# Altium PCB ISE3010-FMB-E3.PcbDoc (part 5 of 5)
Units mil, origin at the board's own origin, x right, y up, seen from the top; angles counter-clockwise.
Board outline 7874.02 x 2362.2 mil, 4 copper layers (Top Layer, MidLayer1, MidLayer2, Bottom Layer), stack 55.6 mil thick; 507 components, 331 nets, 1707 pads, 610 vias.
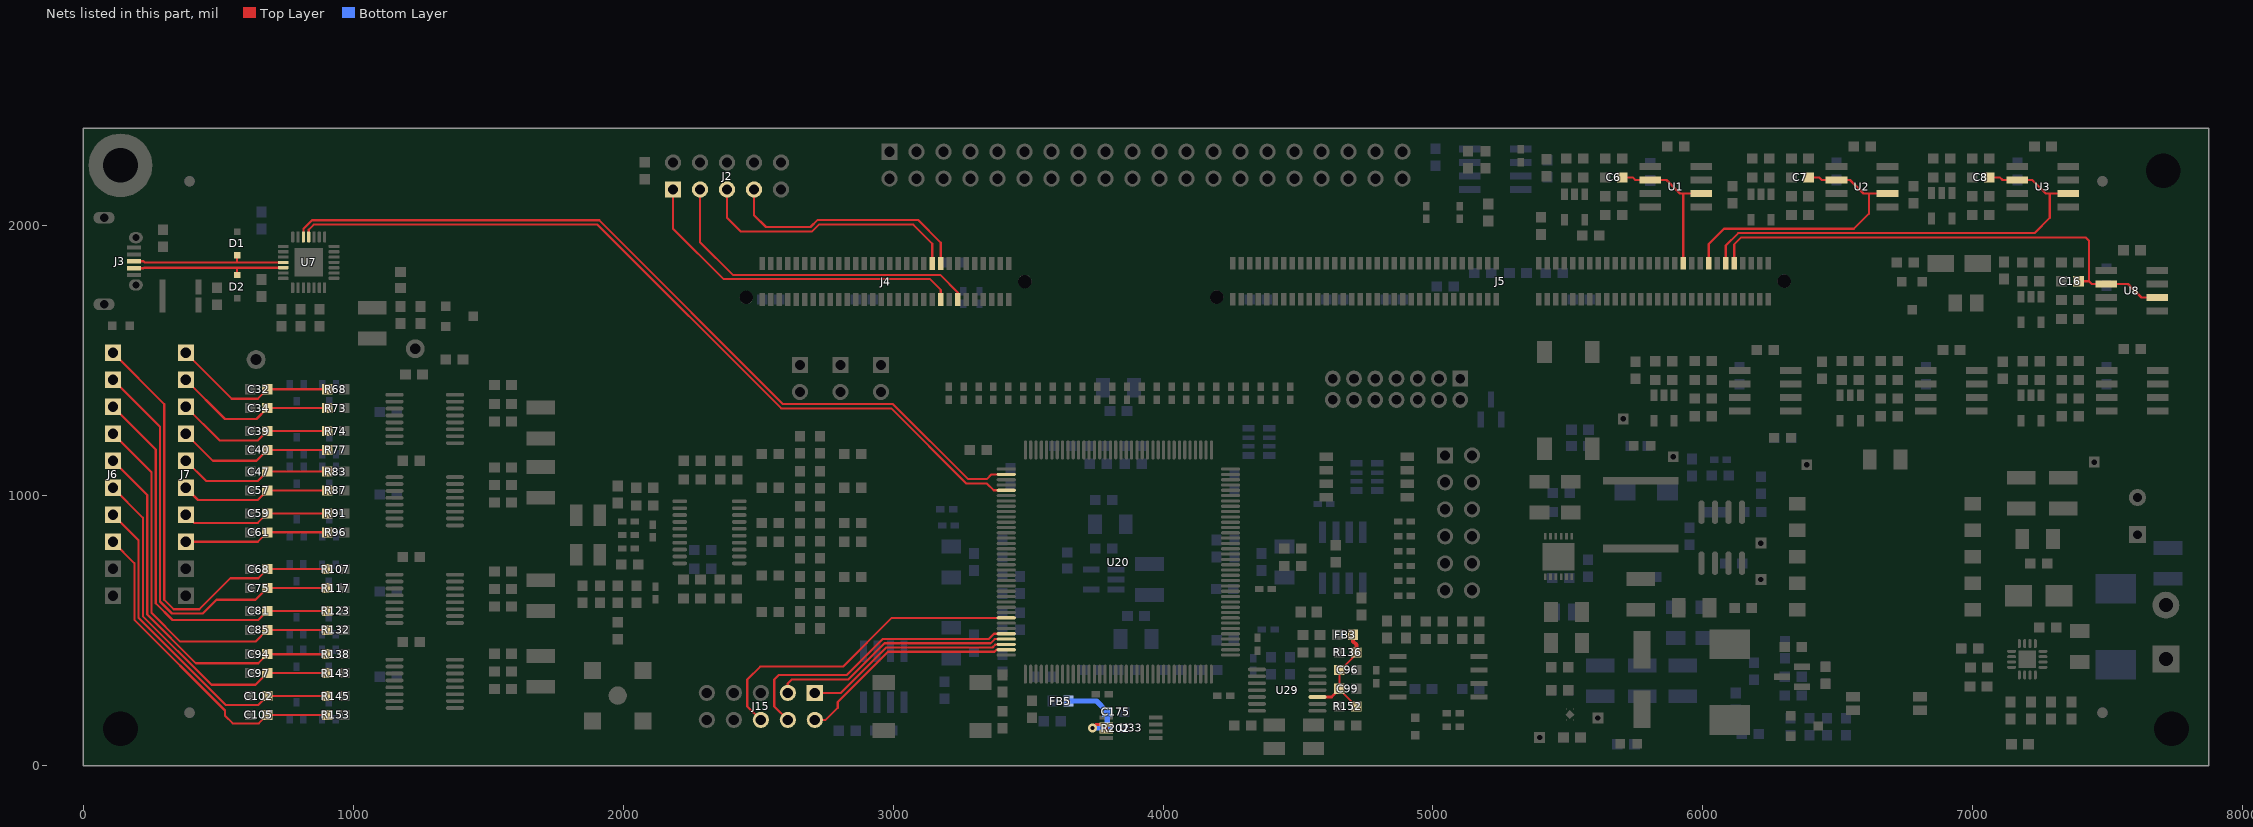
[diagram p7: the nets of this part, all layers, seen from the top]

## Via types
v1: diameter 32, hole 16, Top Layer to Bottom Layer, tented both sides, 495 vias
v2: diameter 26, hole 12, Top Layer to Bottom Layer, tented both sides, 104 vias
v3: diameter 20, hole 8, Top Layer to Bottom Layer, tented both sides, 10 vias
v4: diameter 30, hole 16, Top Layer to Bottom Layer, tented both sides, 1 vias

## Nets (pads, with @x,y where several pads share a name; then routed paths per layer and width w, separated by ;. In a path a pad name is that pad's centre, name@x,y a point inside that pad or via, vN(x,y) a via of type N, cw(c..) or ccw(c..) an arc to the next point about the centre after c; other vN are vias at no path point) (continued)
SC_ALARM_FPGA: J15.6 U20.29 | length 1224.5
  Top Layer w8: J15.6@2510,170 2460,220 2460,320 2507.4,367.4 2814.43,367.4 2995.18,548.15 U20.29@3419.29,548.15
SH_U_ADCIN: C16.2 J5.9 U8.2 U8.6 | length 1867.1
  Top Layer w8: J5.9@6116.14,1861.93 6116.14,1931.65 6142.19,1957.7 7417.3,1957.7 7430.31,1944.69 7430.31,1795 ; C16.2@7391.81,1795 7430.31,1795 ; U8.6@7684.31,1735 U8.6@7684,1735 7625,1735 7575,1785 U8.2@7495,1785 7440.31,1785 7430.31,1795
SH_V_ADCIN: C8.2 J5.11 U3.2 U3.6 | length 1715.7
  Top Layer w8: J5.11@6084.65,1861.93 6084.65,1927.44 6130.71,1973.5 7228.5,1973.5 7285,2030 7285,2120 ; C8.2@7061.5,2180 7100,2180 7110,2170 U3.2@7165,2170 7220,2170 7270,2120 7285,2120 ; U3.6@7354,2120 7285,2120
SH_W_ADCIN: C7.2 J5.15 U2.2 U2.6 | length 1103
  Top Layer w8: J5.15@6021.65,1861.93 6021.65,1932.8 6078.16,1989.3 6559.3,1989.3 6615,2045 6615,2120 ; C7.2@6391.5,2180 6430,2180 6440,2170 U2.2@6495,2170 6545.07,2170 6595.07,2120 6615,2120 ; U2.6@6684,2120 6615,2120
SPI_CLK: J2.1 J4.138 | length 1266.9
  Top Layer w8: J2.1@2185,2135 2185,1990 2372.2,1802.8 3137.2,1802.8 3176.91,1763.09 J4.138@3176.91,1727.07
SPI_CLK_FPGA: J15.3 U20.33 | length 912.4
  Top Layer w8: J15.3@2610,270 2610,305 2625,320 2834.07,320 2968.27,454.2 3361.54,454.2 3376.75,469.41 U20.33@3419.29,469.41
SPI_MISO: J2.7 J4.137 | length 928.5
  Top Layer w8: J2.7@2485,2135 2485,2040 2529.2,1995.8 2693.88,1995.8 2720.68,2022.6 3092.4,2022.6 3176.91,1938.09 J4.137@3176.91,1860.93
SPI_MISO_FPGA: J15.1 U20.34 | length 783.6
  Top Layer w8: J15.1@2710,270 2806.41,270 2974.81,438.4 3368.09,438.4 3378.52,448.83 ; 3378.67,448.67 3379.72,449.72 U20.34@3419.29,449.72
SPI_MOSI: J2.3 J4.134 | length 1253.3
  Top Layer w8: J2.3@2285,2135 2285,1940 2406.4,1818.6 3174.4,1818.6 3239.9,1753.1 J4.134@3239.9,1727.07
SPI_MOSI_FPGA: J15.2 U20.35 | length 829.4
  Top Layer w8: J15.2@2710,170 2750,170 2795,215 2795,236.24 2981.36,422.6 3375.58,422.6 3383.02,430.04 U20.35@3419.29,430.04
SPI_STE: J2.5 J4.139 | length 999.3
  Top Layer w8: J2.5@2385,2135 2385,2030 2435,1980 2700,1980 2725,2005 3075,2005 3145.41,1934.59 J4.139@3145.41,1860.93
SPI_STE_FPGA: J15.4 U20.32 | length 1100
  Top Layer w8: J15.4@2610,170 2560,220 2560,320 2575.8,335.8 2827.52,335.8 2961.72,470 3355,470 3374.09,489.09 U20.32@3419.29,489.09
USB_RS232_RXD: U7.25 U20.5 | length 3026.9
  Top Layer w8: U7.25@835,1959 835,1986 854,2005 1905,2005 2585.8,1324.2 2993.46,1324.2 3271.54,1046.12 3347.47,1046.12 3373,1020.59 U20.5@3419.29,1020.59
USB_RS232_TXD: U7.26 U20.2 | length 3051.5
  Top Layer w8: U7.26@815.3,1959 815.3,1988.64 847.46,2020.8 1911.54,2020.8 2592.34,1340 3000,1340 3278.08,1061.92 3346.92,1061.92 3364.65,1079.65 U20.2@3419.29,1079.65
USBB_N: D2.2 J3.2 U7.5 | length 581
  Top Layer w8: J3.2@187.76,1843.5 223,1843.5 224.8,1845.3 570,1845.3 ; D2.2@570,1818.31 570,1845.3 ; U7.5@741,1845.3 570,1845.3
USBB_P: D1.2 J3.3 U7.4 | length 581.6
  Top Layer w8: J3.3@187.76,1869 223,1869 227,1865 570,1865 ; D1.2@570,1891.69 570,1865 ; U7.4@741,1865 570,1865
VCC_CLK_A: C175.2 FB5.2 R202.1 U33.2 U33.3 | length 357.5
  Top Layer w12: v1(3739,140) 3752.4,153.4 U33.2@3789.8,153.4 U33.3@3789.8,127.8
  Bottom Layer w20: FB5.2@3649.53,240 3753.5,240 C175.2@3793.5,200 R202.1@3793.5,140 3746.2,140 3745.6,140.6 3745,140 v1(3739,140)
VCC_CLK_B: C96.2 C99.2 FB3.2 R136.2 R152.2 U29.3 | length 415.3
  Top Layer w8: R152.2@4716.5,220.32 4653.5,283.31 C99.2@4653.5,285.32 4653.5,350.32 4716.5,413.31 R136.2@4716.5,415.32
  Top Layer w10: U29.3@4572.2,254.73 4624.92,254.73 C99.2@4653.5,283.31
  Top Layer w15: FB3.2@4704.53,485.32 4704.53,460.47 4716.5,448.5 R136.2@4716.5,415.32
VDC_ADCIN: C6.2 J5.21 U1.2 U1.6 | length 576.6
  Top Layer w8: C6.2@5701.5,2180 5740,2180 5750,2170 U1.2@5805,2170 5865,2170 5915,2120 5930,2120 ; J5.21@5927.17,1861.93 5927.17,2117.17 5930,2120 ; U1.6@5994,2120 5930,2120
VOUT_U_PH: C47.2 J7.5 R83.1 | length 569.1
  Top Layer w8: J7.5@380,1130 455,1055 646.5,1055 C47.2@681.5,1090 R83.1@903.5,1090
VOUT_U_PH_FPGA: C94.2 J6.5 R138.1 | length 1377.5
  Top Layer w8: J6.5@110,1130 236.7,1003.3 236.7,560.33 417.03,380 647.95,380 C94.2@681.5,413.54 R138.1@903.5,413.54
VOUT_U_SH: C32.2 J7.1 R68.1 | length 608.4
  Top Layer w8: J7.1@380,1530 550,1360 646.5,1360 C32.2@681.5,1395 R68.1@903.5,1395
VOUT_U_SH_FPGA: C68.2 J6.1 R107.1 | length 1673.1
  Top Layer w8: J6.1@110,1530 300,1340 300,615.2 335.2,580 430,580 545,695 647.95,695 C68.2@681.5,728.54 R107.1@903.5,728.54
VOUT_V_PH: C57.2 J7.6 R87.1 | length 556.6
  Top Layer w8: J7.6@380,1030 425,985 646.5,985 C57.2@681.5,1020 R87.1@903.5,1020
VOUT_V_PH_FPGA: C97.2 J6.6 R143.1 | length 1327.9
  Top Layer w8: J6.6@110,1030 220.9,919.1 220.9,553.79 474.69,300 637.95,300 C97.2@681.5,343.54 R143.1@903.5,343.54
VOUT_V_SH: C34.2 J7.2 R73.1 | length 600.1
  Top Layer w8: J7.2@380,1430 525,1285 641.5,1285 C34.2@681.5,1325 R73.1@903.5,1325
VOUT_V_SH_FPGA: C75.2 J6.2 R117.1 | length 1570.3
  Top Layer w8: J6.2@110,1430 284.1,1255.9 284.1,608.76 328.66,564.2 442.82,564.2 493.62,615 637.95,615 C75.2@681.5,658.54 R117.1@903.5,658.54
VOUT_W_PH: C59.2 J7.7 R91.1 | length 550.4
  Top Layer w8: J7.7@380,930 410,900 646.5,900 C59.2@681.5,935 R91.1@903.5,935
VOUT_W_PH_FPGA: C102.2 J6.7 R145.1 | length 1267.9
  Top Layer w8: J6.7@110,930 205.1,834.9 205.1,547.24 527.34,225 647.95,225 C102.2@681.5,258.54 R145.1@903.5,258.54
VOUT_W_SH: C39.2 J7.3 R74.1 | length 589.8
  Top Layer w8: J7.3@380,1330 505,1205 646.5,1205 C39.2@681.5,1240 R74.1@903.5,1240
VOUT_W_SH_FPGA: C81.2 J6.3 R123.1 | length 1468.2
  Top Layer w8: J6.3@110,1330 268.3,1171.7 268.3,602.21 330.51,540 647.95,540 C81.2@681.5,573.54 R123.1@903.5,573.54
VOUTD_1: C40.2 J7.4 R77.1 | length 581.5
  Top Layer w8: J7.4@380,1230 480,1130 641.5,1130 C40.2@681.5,1170 R77.1@903.5,1170
VOUTD_1_FPGA: C85.2 J6.4 R132.1 | length 1435.5
  Top Layer w8: J6.4@110,1230 252.5,1087.5 252.5,566.88 359.38,460 637.95,460 C85.2@681.5,503.54 R132.1@903.5,503.54
VOUTD_2: C61.2 J7.8 R96.1 | length 538
  Top Layer w8: J7.8@380,830 646.5,830 C61.2@681.5,865 R96.1@903.5,865
VOUTD_2_FPGA: C105.2 J6.8 R153.1 | length 1219.6
  Top Layer w8: J6.8@110,830 189.3,750.7 189.3,540.7 525,205 525,185.68 553.64,157.05 650,157.05 C105.2@681.5,188.54 R153.1@903.5,188.54
pads on no net: D13.2 FID1.1 FID2.1 FID3.1 FID4.1 FID5.1 FID6.1 FID7.1 FID8.1 J4.122 J4.124 J4.125 J4.126 J4.129 J4.136 J4.147 J4.148 J4.149 J4.150 J4.151 J4.152 J4.153 J4.155 J4.159 J4.162 J4.163 J4.164 J4.165 J4.166 J4.167 J4.168 J4.169 J4.170 J4.171 J4.172 J4.173 J4.174 J4.175 J4.176 J4.177 J4.178 J4.181 J4.182 J5.1 J5.2 J5.3 J5.4 J5.5 J5.6 J5.8 J5.13 J5.16 J5.17 J5.20 J5.23 J5.24 J5.25 J5.26 J5.27 J5.28 J5.29 J5.30 J5.31 J5.32 J5.33 J5.34 J5.36 J5.37 J5.39 J5.40 J5.41 J5.42 J5.43 J5.44 J5.45 J5.51 J5.52 J5.55 J5.56 J5.59 J5.60 J5.61 J5.63 J5.64 J5.66 J5.68 J5.70 J5.72 J5.74 J5.77 J5.79 J5.80 J5.81 J5.82 J5.85 J5.86 J5.87 J5.88 J5.90 J5.92 J5.93 J5.94 J5.95 J5.96 J5.113 J5.114 J5.115 J5.116 J5.117 J5.118 J5.119 J5.120 J5.121 J5.122 J11.12 J11.14 Logo1.0 MH2.1 MH3.1 MH4.1 R167.2 T1.3 T1.8 U1.1 U1.5 U1.8 U2.1 U2.5 U2.8 U3.1 U3.5 U3.8 U7.1 U7.2 U7.10 U7.12 U7.13 U7.14 U7.15 U7.16 U7.17 U7.18 U7.19 U7.20 U7.21 U7.22 U7.23 U7.24 U7.27 U7.28 U8.1 U8.5 U8.8 U13.1 U13.5 U13.8 U14.1 U14.5 U14.8 U15.1 U15.5 U15.8 U20.1 U20.6 U20.22 U20.44 U20.50 U20.57 U20.66 U20.67 U20.72 U20.74 U20.75 U20.78 U20.79 U20.93 U20.104 U20.105 U20.143 U33.7 U33.8 U34.3 U35.3 U36.4 U37.1

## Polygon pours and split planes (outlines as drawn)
NetC84_1 on Top Layer "Top Layer-No Net 1" (hatched 90Degree grid 5 track 10, remove dead copper, pour order 67): 7200,531 7220,551 7220,675 7090,675 7060,705 6965,705 6950,690 6950,550 6965,535 7090,535 7120,505 7120,430 7125,425 7152,425 7152,438 7160,446 7200,446
+24VDC_FIL on Top Layer "Top Layer-No Net 1" (hatched 90Degree grid 5 track 10, remove dead copper, pour order 64): 7225,720 7225,770 7210,785 7210,875 7225,890 7396,890 7425,861 7425,605 7450,580 7599,580 7615,596 7615,730 7635,750 7785,750 7795,760 7795,890 7780,905 7545,905 7450,1000 7090,1000 7070,1020 6980,1020 6965,1005 6965,855 6980,840 7080,840 7130,790 7130,725 7145,710 7215,710
NetC139_1 on Top Layer "Bottom Layer-No Net 6" (solid, pour order 88): 5913,965 5952,926 5956,922 5985.02,922 5988,922 6001,935 6005,939 6005,976 6005,992 5983,1014 5968,1029 5948,1029 5916,1029 5913,1026
DGND on Top Layer "Bottom Layer-No Net 6" (solid, pour order 87): 5931,684 5881,684 5854,657 5854,586 5864,576 5916,576 5937,597 5937,678
EARTH on Top Layer "Top Layer-No Net 5" (solid, pour order 60): 120,2050 120,1670 40,1670 35,1670 35,2265 50,2280 65,2295 185,2295 195,2285 210,2285 210,2130 120,2040
+1.25VREF on Top Layer "Top Layer-No Net 1" (hatched 90Degree grid 5 track 10, remove dead copper, pour order 46): 6755,1770 6685,1770 6675,1780 6655,1800 6655,1900 6655,1930 6665,1940 6670,1945 6700,1945 6745,1945 6750,1940 6755,1935 6755,1920 6755,1910 6735,1890 6735,1855 6735,1835 6755,1815 6755,1790 6755,1770
+3.3V_DVDD on Top Layer "Top Layer-No Net 1" (hatched 90Degree grid 5 track 10, remove dead copper, pour order 47): 6955,1665 6900,1665 6800,1765 6800,1815 6820,1835 6820,1935 6835,1950 6915,1950 6935,1930 6935,1780 6960,1755 6960,1670
DGND on Top Layer "Top Layer-No Net 1" (hatched 90Degree grid 5 track 10, remove dead copper, pour order 48): 7095,1670 7005,1670 6995,1680 6995,1705 6995,1915 7010,1930 7015,1935 7055,1935 7065,1925 7070,1920 7070,1875 7070,1785 7095,1760 7100,1755 7100,1735 7100,1675 7095,1670
NetC139_1 on Top Layer "Top Layer-No Net 1" (hatched 90Degree grid 5 track 10, remove dead copper, pour order 69): 5610,965 5590,985 5590,1090 5615,1115 5845,1115 5895,1165 6050,1165 6060,1155 6060,1040 6045,1025 6025,1025 6005,1005 6005,965
+3.3V_DVDD on Top Layer "Top Layer-No Net 1" (hatched 90Degree grid 5 track 10, remove dead copper, pour order 71): 5830,665 5645,666 5620,691 5620,890 5635,905 5920,905 5935,890 5935,800 5850,715 5850,685
NetC79_1 on Top Layer "Top Layer-No Net 1" (hatched 90Degree grid 5 track 10, remove dead copper, pour order 74): 5385,705 5450,705 5455,700 5455,350 5445,340 5390,340 5380,350 5380,700
NetC101_1 on Top Layer "Top Layer-No Net 1" (hatched 90Degree grid 5 track 10, remove dead copper, pour order 78): 5490,300 5525,300 5530,295 5530,250 5498.78,218.78 5494.58,214.67 5490.78,210.8 5485,205 5475,205 5475,240 5485,250 5485,295
+1.8V on Top Layer "Top Layer-No Net 1" (hatched 90Degree grid 5 track 10, remove dead copper, pour order 77): 5501,167 5501,75 5491,65 5390,65 5375,80 5375,165 5385,175 5400,175 5492,176
DGND on Top Layer "Top Layer-No Net 1" (hatched 90Degree grid 5 track 10, remove dead copper, pour order 81): 6635,1170.43 6495.43,1170.43 6490,1165 6490,1110 6495,1105 6595,1105 6630,1105 6635,1110 6635,1170
GND on Top Layer "Top Layer-No Net 1" (hatched 90Degree grid 5 track 10, remove dead copper, pour order 80): 6715,1170.43 6854.57,1170.43 6860,1165 6860,1110 6855,1105 6755,1105 6720,1105 6715,1110 6715,1170
+5V_CNTL on Top Layer "Top Layer-No Net 1" (hatched 90Degree grid 5 track 10, remove dead copper, pour order 73): 5455.16,849.8 5415.79,849.8 5395,850 5390,845 5390,790 5385,785 5360,785 5355,790 5355,965 5365,975 5565,975 5575,965 5575,930 5555,910 5495,910 5480,925 5450,925 5435,910 5435,891 5455.16,870.84
NetD7_2 on Top Layer "Bottom Layer-No Net 6" (solid, pour order 50): 6325,705 6305,701 6288,689 6273,672 6264,651 6260,627 6260,569 6286,543 6374,543 6381,544 6385,545 6388,547 6394,553 6396,556 6397,562 6397,682 6396,690 6394,695 6390,700 6386,703 6380,705
"+6.0 VDD" on Top Layer "Top Layer-No Net 1" (hatched 90Degree grid 5 track 10, remove dead copper, pour order 76): 6160,101 6139,80 5705,80 5700,85 5700,120 5690,130 5617,130 5573,174 5573,203 5560,216 5560,285 5565,290 5975,290 6034,231 6153,231 6160,224
"+6.0 VDD" on Top Layer "Bottom Layer-No Net 6" (solid, pour order 59): 5517,383 5545,383 5588,340 5648,280 5648,266 5570,266 5560,276 5555,281 5555,288 5555,304 5538,321 5527,332 5512,332 5495,332 5482,345 5482,351 5482,383
+3.3V_DVDD on MidLayer2 "Bottom Layer-No Net 6" (solid, remove dead copper, pour order 90): 5295,746 5418,746 5453,781 5453,906.5 5485.5,939 5636,939 5878.5,696.5 5798,616 5643,616 5470,443 5470,272.97 5448,250.97 5337.03,250.97 5122,466 5122,690 5179,747
+5V_CNTL on MidLayer2 "Top Layer-No Net 1" (hatched 90Degree grid 5 track 10, remove dead copper, pour order 51): 5335,780 5390,780 5415,805 5415,965 5415,1215 5350,1280 5345,1285 5345,1400 5345,1645 5360,1660 5410,1660 6342.09,1660 6350,1667.91 6350,1938.54 6343.54,1945 6325,1945 2410.53,1945 2400,1934.47 2400,1670 2410,1660 2450,1660 5185,1660 5195,1650 5195,1625 5195,1210 5285,1120 5295,1110 5295,1035 5295,800 5315,780 5335,780
+3.3V_DVDD on MidLayer2 "Top Layer-No Net 1" (hatched 90Degree grid 5 track 10, remove dead copper, pour order 57): 5885,710 6260,710 6310,760 6310,1070 6330,1090 6615,1090 6640,1115 6640,1240 6660,1260 7820,1260 7830,1270 7830,2310 7820,2320 330,2320 310,2300 310,2115 340,2085 970,2085 1000,2055 1000,1860 1045,1815 1315,1815 1345,1785 1345,70 1370,45 5345,45 5370,70 5370,200 5380,210 5435,210 5465,240 5465,310 5455,320 5380,320 5350,350 5350,705 5250,805 5250,1110 5165,1195 5165,1590 5125,1630 2385,1630 2340,1675 2340,1950 2395,2005 6325,2005 6380,1950 6380,1660 6350,1630 5425,1630 5375,1580 5375,1315 5435,1255 5435,880 5560,755 5560,710 5620,650 5825,650
+5V_AVDD on MidLayer2 "MidLayer1-No Net 4" (hatched 90Degree grid 5 track 8, remove dead copper, pour order 62): 1130,1765 1130,1545 1110,1525 1110,1421 1122,1410 1195,1410 1195,1185 1108,1185 1100,1176 1100,1094 1105,1085 1195,1085 1195,880 1107,880 1101,873 1100,736 1112,720 1195,720 1195,510 1109,510 1100,500 1100,416 1109,405 1195,405 1195,40 39.37,39.37 40,1585 625,1585 690,1520 940,1520 980,1560 980,1765 1005,1790 1105,1790
+4.096VREF on MidLayer2 "Top Layer-No Net 1" (hatched 90Degree grid 5 track 10, remove dead copper, pour order 63): 1125,485 1230,485 1230,732 1222,745 1125,745 1125,855 1224,855 1230,865 1230,1099 1223,1110 1125,1110 1125,1160 1230,1160 1229,1426 1218,1435 1130,1435 1130,1515 1200,1585 1275,1585 1290,1570 1290,430 1125,430
+5V_USB on MidLayer2 "MidLayer1-No Net 5" (solid, remove dead copper, pour order 52): 40,1670 620,1670 730,1560 920,1560 940,1580 940,1785 965,1810 965,2036 946,2053 40,2055
DGND on Bottom Layer "MidLayer2-No Net 1" (solid, remove dead copper, pour order 54): 6585,40 6610,65 6610,150 6585,175 6585,435 6535,485 6380,485 6380,970 6270,1080 5490,1080 5490,1448.75 5490,1480 5405,1565 4910,1565 4910,1800 4850,1860 4955,1965 4955,2325 40,2325 40,40
+1.2V on Bottom Layer "Bottom Layer-No Net" (solid, remove dead copper, pour order 66): 4220,715 4200,695 4105,695 4085,715 4085,835 4065,855 3940,855 3925,870 3925,980 3885,1020 3785,1020 3770,1005 3770,790 3755,775 3610,775 3600,765 3600,597 3627,570 3770,570 3785,555 3785,335 3735,335 3735,390 3450,390 3450,1140 4220,1140
NetC139_1 on Bottom Layer "Bottom Layer-No Net 6" (solid, pour order 89): 5733,1115 5723,1125 5697,1125 5625,1125 5596,1096 5582,1082 5582,1015 5582,1009 5605,986 5614,977 5686,977 5748,977 5755,984 5755,1091 5755,1093 5744,1104
"+6.0 VDD" on Bottom Layer "Top Layer-No Net 1" (hatched 90Degree grid 5 track 10, remove dead copper, pour order 75): 5975,290 6042,223 6160,223 6160,100 6140,80 5666,80 5560,186 5560,285 5565,290
+1.25VREF on Bottom Layer "Bottom Layer-No Net 1" (solid, remove dead copper, pour order 68): 5415,2325 5415,1580 5690,1580 5690,1370 5750,1310 5750,1275 5775,1250 7835,1250 7835,2325
DGND on Bottom Layer "Top Layer-No Net 1" (hatched 90Degree grid 5 track 10, remove dead copper, pour order 85): 2930,365 2930,495 2995,560 3088.15,560 3100,548.15 3100,360 3090,350 2945,350
+3.3V_DVDD on Bottom Layer "Top Layer-No Net 1" (hatched 90Degree grid 5 track 10, remove dead copper, pour order 82): 4050,715 4005,715 3995,725 3820,725 3810,735 3810,761.5 3815,766.31 3845,766.31 3880,800 4050,800 4060,790 4060,725
DGND on Bottom Layer "Top Layer-No Net 1" (hatched 90Degree grid 5 track 10, remove dead copper, pour order 84): 4010,430 3930,430 3915,445 3915,583.28 3888.28,610 3888.28,658.28 3900,670 4030,670 4045,655 4045,465
+5V_CNTL on Bottom Layer "Bottom Layer-No Net 2" (hatched 90Degree grid 5 track 8, pour order 61): 2795,1705 2945,1705 2945,2310 2970,2335 2860,2335 2815,2290 2815,1880 2795,1860
NetD23_2 on Bottom Layer "Top Layer-No Net 1" (hatched 90Degree grid 5 track 10, remove dead copper, pour order 49): 7660,335 7770,335 7785,350 7785,455 7780,460 7770,470 7715,470 7440,470 7425,455 7425,385 7425,310 7445,290 7575,290 7605,290 7650,335 7660,335
+3.3V_DVDD on Bottom Layer "Top Layer-No Net 1" (hatched 90Degree grid 5 track 10, remove dead copper, pour order 72): 5770,650 5635,650 5620,665 5620,830 5635,845 5755,845 5780,820 5780,660
+1.8V on Bottom Layer "Top Layer-No Net 1" (hatched 90Degree grid 5 track 10, remove dead copper, pour order 79): 5435,60 5375,60 5365,70 5365,165 5375,175 5435,175 5445,165 5445,70
DGND on Bottom Layer "Top Layer-No Net 1" (hatched 90Degree grid 5 track 10, remove dead copper, pour order 83): 3840,790 3810,790 3800,800 3800,860 3835,895 3835,910 3835,945 3830,950 3820,960 3810,960 3800,970 3800,995 3800,1000 3875,1000 3885,990 3905,970 3905,960 3905,875 3865,835 3850,820 3850,805 3850,800 3840,790
NetC78_1 on Bottom Layer "Top Layer-No Net 1" (hatched 90Degree grid 5 track 10, remove dead copper, pour order 70): 6050,560 6060,570 6060,665 6035,690 5975,690 5970,685 5970,570 5980,560
DGND on Bottom Layer "Top Layer-No Net 1" (hatched 90Degree grid 5 track 10, remove dead copper, pour order 86): 5968,340 5560,340 5540,360 5540,420 5550,430 5630,430 5650,450 5650,485 5655,490 5770,490 5855,405 5967,405 5976,396 5976,348
"+6.0 VDD" on Bottom Layer "Bottom Layer-No Net 6" (solid, remove dead copper, pour order 55): 5863,500 5856,493 5856,454 5864,446 5994,446 6007,433 6007,335 5963,291 5963,263 5985,241 6018,241 6022,245 6022,259 6066,303 6066,479 6045,500
+24VDC_FIL on Bottom Layer "Top Layer-No Net 1" (hatched 90Degree grid 5 track 10, remove dead copper, pour order 58): 7425,605 7450,580 7600,580 7615,595 7615,730 7645,760 7795,760 7795,890 7780,905 7455,905 7425,875
GND on Bottom Layer "Top Layer-No Net 1" (hatched 90Degree grid 5 track 10, remove dead copper, pour order 56): 7795,565 7765,535 7680,535 7655,560 7655,700 7666,723 7781,722 7795,705
GND on MidLayer1 "Top Layer-No Net 1" (solid, remove dead copper, pour order 65): 6723,1180 7804,1179 7829,1152 7830,285 7705,55 6790,55 6775,70 6775,370 6870,465 6950,465 6960,475 6961,1060 6950,1072 6722,1072 6715,1079 6715,1172
DGND on MidLayer1 "MidLayer2-No Net 1" (solid, remove dead copper, pour order 53): 6595,39 6610,51 6610,150 6585,175 6584,465 6564,486 6391,486 6381,497 6380,1064 6396,1080 6624,1080 6640,1092 6640,1229 6665,1250 7798,1251 7836,1276 7835,2325 40,2325 40,40

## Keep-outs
MidLayer1:
  circle w78.74: c137.8,2224.41 r118.11
Bottom Layer:
  circle w78.74: c137.8,2224.41 r118.11
Keep-Out Layer:
  circle w78.74: c137.8,137.8 r118.11
  circle w78.74: c7736.22,137.8 r118.11
  circle w78.74: c7705,2205 r118.11
  lines w10: 0,-5 4950,-5

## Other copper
Top Layer:
  region net +5V_AVDD: 1015,1670 1355,1670 1365,1680 1365,1780 1355,1790 1030,1790 1015,1775
  region net +5V_USB: 415,1735 510,1735 540,1705 690,1705 715,1730 715,1810 760,1810 760,1800 770,1790 780,1790 780,1725 765,1710 765,1675 755,1665 425,1665 415,1675
  pour cut-out: 5735,116 5731,112 5713,112 5715,110 5715,95 5735,95
  text ".Layer_Name" at 577,-858.49 h40
MidLayer2:
  pour cut-out: 5485,736 5485,818 5449,854 5430.11,830 5410.61,747.08 5443,715 5465,715.24
  pour cut-out: 6980,720 6980,880 6900,880 6900,720
  pour cut-out: 815,1540 815,1598.54 735,1598.54 735,1540
  pour cut-out: 5201.69,1140 5201.69,1189.98 5175,1205 5150,1180 5121.69,1140
  pour cut-out: 5475,25 5475,330 5345,200 5284.69,83.54 5284.69,25
  pour cut-out: 6040,690 5957.91,771 5907.91,701 5907.91,690
  pour cut-out: 6611.69,825 6611.69,883.54 6531.69,883.54 6531.69,825
  pour cut-out: 3763,29 3736,56 3736,122 3637.69,87.54 3637.69,29
  text ".Layer_Name" at 577,-858.49 h40
MidLayer1:
  pour cut-out: 7785,305 7785,455 7770,470 7655,470 7640,455 7640,310 7655,295 7775,295
  pour cut-out: 6610,770 6610,785 6590,785 6590,770
  pour cut-out: 3826.79,2130.33 3826.79,2175 3806.79,2175 3806.79,2130.33
  pour cut-out: 3731.18,117.35 3630.36,92.33 3630.36,29.72 3753.64,30.28 3731.18,53.6
  text ".Layer_Name" at 577,-858.49 h40
Bottom Layer:
  pour cut-out: 3798.32,549 3798.32,509.42 3826,509.42 3828,534 3841,549
  pour cut-out: 4071,834 4064,843 4052,848 3934,850 3909.71,870 3869.05,816.74 4056,814 4071,814
  pour cut-out: 3787,673.6 3772,673.6 3772,631.6 3787,631.6
  pour cut-out: 3767.22,765.59 3673,770 3673,743 3774,743 3766,707 3793,707 3794,748 3848,790 3780,790
  pour cut-out: 6640,1945 6640,1605 5420,1605 5420,1945
  pour cut-out: 6175,230 6169.11,177.62 6225.24,230
  pour cut-out: 6055,243.33 6055,280 6032.96,267.9 6032.96,243.33
  pour cut-out: 6335,315 6333.7,368.82 6311.35,368.82 6311.35,353.82
  pour cut-out: 6620,97.54 6615,105 6610,115 6610,205 6555.98,205 6555,105 6558.7,83.82 6570,70.77 6570,50 6555,35 6600,35 6620,55
  pour cut-out: 6380,85 6435,145 6345,145 6350,245 6265,245 6225.34,197.11 6225.34,159.91 6165,85
  pour cut-out: 6505,83.82 6505,206.18 6485,206.18 6485,83.82
  pour cut-out: 5504.43,622.68 5555,675 5570,650 5615,650 5577.22,725 5515,725 5460,670 5410,655 5410,596.54
  pour cut-out: 6135,880 6135,915 6125,930 6100,930 6100,915
  pour cut-out: 6243.7,960 6243.7,1105 6080,1105 6080,960
  pour cut-out: 5536.18,873.26 5536.18,1040 5476.81,1040 5476.81,873.26
  pour cut-out: 6126.18,1045 6126.18,1060 5985,1060 5985,1045
  pour cut-out: 6580,840 6580,855 6560,855 6560,840
  pour cut-out: 5455,2110 5455,2345 5375,2345 5375,2105 5415,2069.81
  pour cut-out: 3820,1335 3820,1495 3740,1495 3740,1335
  pour cut-out: 4580,1745 4597.18,1797.82 4585,1810 4585,1910 4345,1945 4405,1885 4405,1830 4415.34,1715 4445,1745
  pour cut-out: 3110,845 3159.22,970.78 3105,1025 3030,1025 3030,845
  pour cut-out: 3015,633.21 3015,885 2935,885 2935,550
  pour cut-out: 3331.54,1541.73 3331.54,1701.73 3251.54,1701.73 3251.54,1541.73
  pour cut-out: 2165,1850 2165,2010 2085,2010 2085,1850
  pour cut-out: 2263.08,1202.43 2297.27,1168.24 2470,1725 2395,1796 2354,1755 2230,1755 2190,1795 2170,1755 2070,1455 1760,1140 1805,1100 1944.21,1202.43
  pour cut-out: 1465,1096.67 1465,1240 1375,1240 1375,1080 1425,1030 1420,865 1475,920 1525,935 1480,980
  pour cut-out: 863,175 860,356 780,356 775,236 750,205 742.6,197.8 783.1,174.1 804.1,195.1 843,195
  pour cut-out: 1095,191 1095,979.9 755,979.9 755,191
  pour cut-out: 1084.93,1428.86 1063,1451.43 968,1440 915,1440 895,1420 875,1420 855,1440 795.53,1440 780,1425.25 780,1396 765,1396 765,1185 749,1185 740,1176 740,841 740.38,811.79 775,826 875,826 893,875 1085.03,872.6
  pour cut-out: 4418,239.15 4458,430 4428,430 4428,510 4215,510 4215,385 4163,300 4115,300 4125,216 4240,235
  pour cut-out: 5336,70 5358,206 5328,236 5256,165 5206,165 5146,225 5146,315 4901,315 4813,225 4403,226 3511,265 3443,176 3443,76 4403,66
  pour cut-out: 6835,790 6835,950 6755,950 6755,790
  pour cut-out: 2619.94,2285 2400,2285 2400,2205 2619.94,2205
  pour cut-out: 3126.59,2305.64 3111.59,2305.64 3111.59,2275 3126.59,2275
  pour cut-out: 3110,2315 3015,2315 3015,2235 3084.39,2235 3110,2279.56
  pour cut-out: 4950,2335 3270.61,2335 3270,2170 3477.01,1985 3740,1985 3731.53,2061.27 4620,2066.26 4620,2180 4670,2230 4925,2230 4965,2190
  pour cut-out: 2955,1635 2770,1634.36 2770,1571.46 2893.16,1571.46
  pour cut-out: 2668.27,2067.8 2508.27,2067.8 2508.27,1976.54 2668.27,1976.54
  pour cut-out: 1370,578.61 1370,405 1470.25,405 1470.25,578.61
  text ".Layer_Name" at 577,-858.49 h40

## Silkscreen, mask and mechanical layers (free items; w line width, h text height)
Top Overlay:
  drawing of 248 lines, arcs and shapes, not listed
  text "A" at 7059,2305 h40
  text "B" at 6295,2300 h40
  text "ISE3010-FMB-E3" at 1250,2030 h80
  text "A" at 7681,2017 h40
  text "B" at 3705,1761 h40
  text "D" at 2140,1705 h40
  text "C" at 4430,1260 h40
  text "1" at 4955.75,1170 h40
  text "2" at 5231.95,1148 h40
  text "12" at 5223.97,637 h40
  text "D" at 1855,505 h40
  text "TIDA-00080-B" at 640,45 h80
  text "C" at 4680,45 h40
  text ".Layer_Name" at 577,-858.49 h40
Bottom Overlay:
  circle w25: c3860,766 r6
  circle w25: c4669.5,1164.5 r6
  circle w25: c4262,1254 r6
  circle w10: c5251,1232 r1.41
  lines w6: 3471,83 3490,83 3535,128 3538,128 ; 3828,307 3831,310 3831,320 ; 4144,450 4164,450 ; 5123,2107 5085,2107 5085,2310 5381,2310 5381,2107 5159,2107 ; 6370,72 6244,72 6244,208 6267,231 6267,535 6543,535 6543,522 6543,224 6598,224 6598,79 ; 6416,73 6528,73 ; 7410,570 7650,570 ; 7410,585 7650,585 ; 7410,725 7650,725 ; 2863,180 2863,479 3066,479 3066,180 2863,180 ; 4285,1125 4285,1275 4425,1275 4425,1125 4285,1125 ; 4550,625 4550,920 4770,920 4770,625 4550,625 ; 4685,995 4685,1150 4825,1150 4825,995 4685,995
  text "REV E3" at 595,45 h80
  text "TIDA-00080-B" at 1100,44.06 h80
  text ".Layer_Name" at 577,-858.49 h40
Top Paste:
  region: 5490.78,204.25 5492.78,204.25 5498.78,210.25 5498.78,217.35 5490.78,217.35
  region: 5524.18,204.25 5522.18,204.25 5516.18,210.25 5516.18,217.35 5524.18,217.35
  region: 5524.18,175.25 5522.18,175.25 5516.18,169.25 5516.18,162.15 5524.18,162.15
  region: 5490.78,175.25 5492.78,175.25 5498.78,169.25 5498.78,162.15 5490.78,162.15
  text ".Layer_Name" at 577,-858.49 h40
Bottom Paste:
  text ".Layer_Name" at 577,-858.49 h40
Top Solder:
  text ".Layer_Name" at 577,-858.49 h40
  text ".Layer_Name" at 577,-858.49 h40
Bottom Solder:
  text ".Layer_Name" at 577,-858.49 h40
Drill Guide:
  text ".Layer_Name" at 577,-858.49 h40
M1 Board Outline:
  the board outline again, w10
  text "Board Outline" at 510,-846 h40
M2 Board Dimensions:
  rectangle: -0.5,-285.5 124.5,-160.5
  rectangle: 124.5,-410.5 499.5,-285.5
  lines w7: -0.5,-285.5 999.5,-285.5 ; 124.5,-410.5 124.5,-160.5 ; 249.5,-410.5 249.5,-160.5 ; 499.5,-410.5 499.5,-160.5 ; 749.5,-410.5 749.5,-160.5 ; -0.5,-410.5 999.5,-410.5 999.5,-160.5 -0.5,-160.5 -0.5,-410.5
  lines w10: -0.5,-475.5 -0.5,-455.5 ; 59.5,-485.5 -0.5,-465.5 ; 59.5,-445.5 -0.5,-465.5 ; 223.58,-465.5 -0.5,-465.5 ; 775.42,-465.5 999.5,-465.5 ; 939.5,-485.5 999.5,-465.5 ; 939.5,-445.5 999.5,-465.5 ; 999.5,-475.5 999.5,-455.5
  text "1000 (mil)" at 233.58,-501.49 h60
M3 3D STEP Top:
  text ".Layer_Name" at 577,-858.49 h40
M4 3D STEP Bottom:
  text ".Layer_Name" at 577,-858.49 h40
M5 Assembly Top:
  circle w12: c5564,2121 r6
  circle w12: c6254,2122 r6
  circle w12: c6922,2124 r6
  circle w12: c1346,1706 r6
  circle w12: c7253.6,1737.24 r6
  circle w12: c7255,1374 r6
  circle w12: c6326.6,186.76 r6
  circle w12: c6585,1374 r6
  circle w12: c5894,1372 r6
  circle w10: c5469,154 r4
  circle w14: c4868,405 r6
  circle w12: c6812.5,1792.5 r6
  circle w20: c6397.4,292.6 r6
  lines w1: 5756.5,65.25 5756.5,96.75 ; 5806.5,1169.25 5806.5,1200.75 ; 6326.5,1199.25 6326.5,1230.75
  lines w6: 8.21,1629.96 33.21,1629.96 ; 33.21,1604.96 33.21,1654.96 ; 58.21,1629.96 83.21,1629.96 ; 269.45,1830.55 269.45,1649.45 450.55,1649.45 450.55,1830.55 271,1830.55 ; 1147.31,1768.5 1147.31,1831.5 ; 1202.68,1768.5 1202.68,1831.5 ; 4508.5,542.32 4571.5,542.32 ; 4508.5,597.69 4571.5,597.69 ; 4643.5,457.63 4703,457.63 ; 4643.5,513 4706.5,513 ; 4910.04,38.21 4960.04,38.21 ; 4919.25,133.58 4919.25,156.42 ; 4935.04,13.21 4935.04,38.21 ; 4935.04,88.21 4935.04,63.21 ; 4950.75,133.58 4950.75,156.42 ; 33.21,1629.96 58.21,1654.96 58.21,1604.96 33.21,1629.96 ; 4935.04,38.21 4910.04,63.21 4935.04,63.21 ; 4935.04,38.21 4960.04,63.21 4935.04,63.21 ; 128.58,1614.25 151.42,1614.25 128.58,1614.25 ; 128.58,1645.75 151.42,1645.75 128.58,1645.75 ; 2411.31,1684.87 2442.1,1654.08 3533.05,1654.08 3533.05,1929.67 2411.31,1929.67 2411.31,1684.87 ; 3856.3,1655 3856.3,1932.8 6643.7,1932.8 6643.7,1655 3856.3,1655 ; 4826.69,229.68 4826.69,429.68 5212.52,429.68 5212.52,229.68 4826.69,229.68 ; 5465.27,1996 5585,1996 5585,2148 5465.27,2148 5465.27,1996 ; 5795.27,1247 5795.27,1399 5915,1399 5915,1247 5795.27,1247 ; 6155.27,1997 6275,1997 6275,2149 6155.27,2149 6155.27,1997 ; 6486.27,1249 6606,1249 6606,1401 6486.27,1401 6486.27,1249 ; 6823.27,1999 6943,1999 6943,2151 6823.27,2151 6823.27,1999 ; 7154.87,1612.24 7154.87,1764.24 7274.6,1764.24 7274.6,1612.24 7154.87,1612.24 ; 7156.27,1249 7156.27,1401 7276,1401 7276,1249 7156.27,1249
  lines w10: -292,-930.17 6308,-930.17 ; -292,-726.83 6310,-726.83 ; -292,-523.5 -292,-1133.5 3713,-1133.5 6310,-1133.5 6310,-523.5 -291.5,-523.5 -291.5,-1133.5 1284,-1133.5 ; 2173,-1133.5 2173,-523.5 ; 3440,-726.83 3440,-523.5 ; 4280,-726.83 4280,-523.5 ; 4902,-1140 4902,-937.17
  text "1" at 2876,2267 h36
  text "39" at 4982,2265 h36
  text "2" at 2866,2156 h36
  text "40" at 4980,2147 h36
  text "119" at 4174.77,1891.14 h36
  text "1" at 6236.45,1890.54 h36
  text "57" at 5219.11,1889.58 h36
  text "179" at 2435,1888.23 h36
  text "121" at 3446.39,1844.46 h36
  text "1" at 225,1795 h36
  text "FB1" at 1193,1764 h36 r90
  text "U9" at 325,1731 h36
  text "122" at 3422.53,1662.83 h36
  text "2" at 6232.98,1662.84 h36
  text "180" at 2434.74,1660.51 h36
  text "120" at 4177.66,1661.35 h36
  text "56" at 5349.45,1660.64 h36
  text "D3" at 205,1600 h36
  text "1" at 5092,1478 h36
  text "13" at 4586,1474 h36
  text "2" at 5088,1274 h36
  text "14" at 4576,1270 h36
  text "1" at 5365,1163 h36
  text "FB2" at 4495,552 h36
  text "FB3" at 4627,468 h36
  text "1" at 2957,349 h36
  text "U26" at 4961,327 h36
  text "*" at 7575,320 h60
  text "D9" at 4902,118 h36 r90
  text "COMPONENTS MARKED 'DNP' SHOULD NOT BE POPULATED." at 1153.5,-318.5 h40
  text "ASSEMBLY VARIANT:" at 1153,-434 h40
  text ".VariantName" at 2189,-434 h40
  text ".PRJ_Number" at 2813,-652 h40
  text "PCB VIEWED FROM TOP SIDE" at -228.5,-655.67 h40
  text "BOARD #:" at 2248,-655.67 h40
  text "REV:" at 3638,-655.67 h40
  text "E3" at 3929.5,-655.67 h40
  text "SVN REV:" at 4476,-655.67 h40
  text ".VersionControl_RevNumber" at 4982,-655.67 h40
  text "LAYER NAME: ASSEMBLY TOP" at -235,-839 h40
  text ".PRJ_Title" at 2245,-852 h40
  text "PLOT NAME =" at -228.5,-1064.34 h40
  text ".plot_File_Name" at 577,-1064.34 h40
  text "GENERATED    :" at 2250,-1064.34 h40
  text ".Print_Date" at 3119.5,-1064.34 h40
  text ".Print_Time" at 3848.5,-1064.34 h40
  text "TEXAS INSTRUMENTS" at 5113,-1064.34 h40
M6 Assembly Bottom:
  circle w25: c4659,1120 r6
  circle w25: c4264,1250 r6
  circle w25: c2889,425 r6
  circle w25: c5326,2285 r6
  circle w10: c5281,1278 r5
  rectangle: 4503,894 4543,934
  lines w6: 3588.5,212.31 3651.5,212.31 ; 3588.5,267.68 3650,267.68 ; 3617.31,728.5 3617.31,791.5 ; 3672.69,728.5 3672.69,791.5 ; 2863,180 3066,180 3066,479 2863,479 2863,180 ; 4550,625 4550,920 4770,920 4770,625 4550,625 ; 5085,2107 5381,2107 5381,2310 5085,2310 5085,2107
  lines w10: -292.5,-727.33 6309.5,-727.33 ; -290.5,-930.67 6309.5,-930.67 ; 1115.5,-1140.5 1115.5,-937.67 ; 1737.5,-727.33 1737.5,-524 ; 2577.5,-727.33 2577.5,-524 ; 3844.5,-1134 3844.5,-524 ; 4733.5,-1134 6309,-1134 6309,-524 -292.5,-524 -292.5,-1134 2304.5,-1134 6309.5,-1134 6309.5,-524
  text "U34" at 5279,2187 h36
  text "U32" at 4715,755 h36
  text "1" at 3860,715 h36
  text "FB4" at 3627,714 h36 r270
  text "U37" at 3000,315 h36
  text "FB5" at 3665,223 h36
  text "COMPONENTS MARKED 'DNP' SHOULD NOT BE POPULATED." at 6102,-318 h40
  text ".VariantName" at 5058,-434 h40
  text "ASSEMBLY VARIANT:" at 6097,-434 h40
  text ".VersionControl_RevNumber" at 1035.5,-656.17 h40
  text "SVN REV:" at 1541.5,-656.17 h40
  text "E3" at 2088,-656.17 h40
  text "REV:" at 2379.5,-656.17 h40
  text ".PRJ_Number" at 3224,-656.17 h40
  text "BOARD #:" at 3769.5,-656.17 h40
  text "PCB VIEWED FROM BOTTOM SIDE" at 6246,-656.17 h40
  text "LAYER NAME: ASSEMBLY BOTTOM" at 6241,-853.84 h40
  text ".PRJ_Title" at 3767,-867 h40
  text "TEXAS INSTRUMENTS" at 904.5,-1064.84 h40
  text ".Print_Time" at 2169,-1064.84 h40
  text ".Print_Date" at 2898,-1064.84 h40
  text "GENERATED    :" at 3767.5,-1064.84 h40
  text ".plot_File_Name" at 5440.5,-1064.84 h40
  text "PLOT NAME =" at 6246,-1064.84 h40
M9 Title Sheet:
  drawing of 57 lines, arcs and shapes, not listed
  text "1" at 739.84,8036.5 h40
  text "2" at 3235.5,8036.5 h40
  text "3" at 5724.84,8036.5 h40
  text "4" at 8231.51,8036.5 h40
  text "5" at 10730.5,8036.5 h40
  text "6" at 13235.5,8036.5 h40
  text "A" at -416.5,6893.5 h40
  text "A" at 14383.5,6893.5 h40
  text "B" at -416.5,4513.5 h40
  text "B" at 14383.5,4513.5 h40
  text "C" at -416.5,2138.5 h40
  text "C" at 14383.5,2138.5 h40
  text "PROJECT TITLE:" at 11343.5,277.5 h40
  text ".PRJ_Title" at 11393.5,144.17 h40
  text "DESIGNED FOR:" at 11343.5,-23.5 h40
  text ".PRJ_Customer" at 11393.5,-163.5 h40
  text "D" at -416.5,-231.5 h40
  text "D" at 14383.5,-231.5 h40
  text "FILE NAME:" at 11343.5,-323.5 h40
  text ".Pcb_File_Name_No_Path" at 11393.5,-443.5 h40
  text "Texas Instruments (TI) and/or its licensors do not warrant the accuracy or completeness of this specification" at 6374,-605.34 h40
  text "ENGINEER:" at 11343.5,-613.5 h40
  text "LAYOUT BY:" at 12848.5,-613.5 h40
  text "or any information contained therein. TI and/or its licensors do not warrant that this design will meet" at 6329.01,-718 h40
  text ".PRJ_Engineer" at 11393.5,-768.49 h40
  text ".PCB_Layout" at 12899,-768.49 h40
  text "the specifications, will be suitable for your application or fit for any particular purpose, or will operate in" at 6329.01,-830.67 h40
  text "ALTIUM DESIGNER VERSION:" at 12848.5,-923.5 h40
  text "an implementation. TI and/or its licensors do not warrant that the design is production worthy. You should" at 6329.01,-943.33 h40
  text "completely validate and test your design implementation to confirm the system functionality for your application." at 6374,-1056 h40
  text ".print_Scale" at 11393.5,-1056.83 h40
  text ".Application_BuildNumber" at 12899,-1056.83 h40
  text "1" at 739.84,-1263.5 h40
  text "2" at 3235.5,-1263.5 h40
  text "3" at 5724.84,-1263.5 h40
  text "4" at 8231.51,-1263.5 h40
  text "5" at 10730.5,-1263.5 h40
  text "6" at 13235.5,-1263.5 h40
M10 Fab Notes:
  drawing of 218 lines, arcs and shapes, not listed
  text "DESIGN INFORMATION" at 12381.02,6810 h60
  text "(REFER ALSO ARRAY/PANEL PROFILING INFORMATION)" at 12019.46,6648.29 h60
  text "BOARD SIZE" at 11333.46,6644 h60
  text "7874MIL" at 11795.78,6516.18 h60
  text "X" at 12301.46,6516.18 h60
  text "2362MIL" at 12532.78,6516.18 h60
  text "Number of Layers :" at 11746.46,6399 h60
  text "4" at 12841.27,6389 h60
  text "MIN. TRACK WIDTH:" at 11746.46,6260 h60
  text "8" at 12842.7,6260 h60
  text "MIL" at 12997.46,6260 h60
  text "MIN. CLEARANCE:" at 11746.46,6128 h60
  text "7.5" at 12842.7,6128 h60
  text "MIL" at 12997.46,6128 h60
  text "MIN. VIA PAD SIZE:" at 11746.46,5996 h60
  text "20" at 12812.71,5996 h60
  text "MIL" at 12997.46,5996 h60
  text "0.15mm (6MIL)" at 12426.46,5889.29 h60
  text "MINIMUM ANNULAR RING" at 11402.23,5885 h60
  text "EXTERNAL" at 13134.46,5885 h60
  text "PER" at 11602.23,5767 h60
  text "IPC-D-275 CLASS 2 LEVEL C" at 11822.23,5767 h60
  text "MIL, HOLES" at 13310.46,5654.71 h60
  text "+/-" at 12918,5654 h60
  text "+/-" at 13772,5654 h60
  text "REGISTRATION TOLERANCES:" at 11402.23,5649 h60
  text "METAL" at 12602,5649 h60
  text "5" at 13178.2,5649 h60
  text "3" at 14011.2,5649 h60
  text "MIL" at 14127.46,5649 h60
  text "IT IS NOT IMPEDANCE CONTROLLED BOARD" at 11651.46,5542 h60
  text "VIA'S ARE TENTED" at 11659,5441 h60
  text "MATERIAL:" at 11333,5309 h60
  text "FR-4 High Tg" at 12318.9,5184.21 h60
  text "FR-408" at 11753.46,5175.64 h60
  text "OTHER" at 13241.46,5175.64 h60
  text "X" at 11610,5175 h60
  text "63 MIL (1.6mm) +/-10%" at 12073.56,5012.92 h60
  text "THICKNESS:" at 11407.23,5008.64 h60
  text "X" at 11945.4,5008.64 h60
  text "OTHER" at 13358.46,5008.64 h60
  text "TOLERANCE:" at 11407.23,4850.64 h60
  text "X" at 12246.53,4850.64 h60
  text "ANSI IPC-6012 TYPE 3 CLASS 2" at 12433.48,4850.64 h60
  text "OTHER +/-" at 12433.46,4694.64 h60
  text "BOW & TWIST:" at 11407.23,4537.64 h60
  text "X" at 12246.53,4537.64 h60
  text "ANSI IPC-6012 TYPE 3 CLASS 2" at 12433.48,4537.64 h60
  text "OTHER +/-" at 12433.46,4379.13 h60
  text "COPPER THICKNESS (FINISHED):" at 11332.46,4243.64 h60
  text "1.4MIL (1oz)" at 12212.46,4090.92 h60
  text "2MIL (1.4oz)" at 12979.46,4090.92 h60
  text "2.8MIL (2oz)" at 13706.46,4090.92 h60
  text "OUTER:" at 11689.46,4086.64 h60
  text "X" at 12085,4085 h60
  text "1.4MIL (1oz)" at 12212.46,3933.92 h60
  text "2.8MIL (2oz)" at 12979.46,3933.92 h60
  text "N/A" at 13706,3934.29 h60
  text "INNER SIGNAL:" at 11400.38,3929.64 h60
  text "X" at 12085,3930 h60
  text "DRILLING:" at 11332.46,3790.64 h60
  text "REFERENCE:" at 11407.23,3673.64 h60
  text "X" at 12055.46,3673.64 h60
  text "AS SHOWN" at 12242.46,3673.64 h60
  text "X" at 12956.46,3673.64 h60
  text "NC_DRILL FILES" at 13093.46,3673.64 h60
  text "PTH MIN COPPER THICKNESS:" at 11407.23,3515.64 h60
  text "X" at 12757.46,3515.64 h60
  text "1MIL" at 12894.46,3515.64 h60
  text "OTHER" at 13391.46,3515.64 h60
  text "BOARD FINISH:" at 11332.46,3356.64 h60
  text "SILKSCREEN:" at 11487.68,3238.64 h60
  text "X" at 12436.46,3238.64 h60
  text "TOP" at 12562.46,3238.64 h60
  text "X" at 12946.46,3238.64 h60
  text "BOTTOM" at 13073.46,3238.64 h60
  text "SILKSCREEN COLOR:" at 11487.68,3071.64 h60
  text "X" at 12435.42,3071.64 h60
  text "WHITE" at 12562.46,3071.64 h60
  text "OTHER" at 13073.46,3071.64 h60
  text "SOLDER RESIST COLOR:" at 11487.68,2901.64 h60
  text "X" at 12055.42,2742.44 h60
  text "GREEN" at 12182.46,2742.44 h60
  text "BLUE" at 12773.46,2742.44 h60
  text "OTHER" at 13311.46,2742.44 h60
  text "IMMERSION GOLD (ENIG)" at 12393.46,2553.92 h60
  text "ENEPIG" at 13731,2550.64 h60
  text "SURFACE FINISH:" at 11332.46,2549.64 h60
  text "X" at 12206.51,2549.64 h60
  text "IMM. TIN/SILVER OR EQUIV" at 11662,2392.64 h60
  text "OTHER" at 13093.46,2392.64 h60
  text "ARRAY/PANEL:" at 11332.46,2213.64 h60
  text "CUT AND TRIM PER MECH LAYER 1" at 12393.46,2209.35 h60
  text "N.C. ROUTE" at 12393.46,2057.64 h60
  text "X" at 13072.46,2057.64 h60
  text "V. SCORE" at 13259.46,2057.64 h60
  text "CERTIFICATION:" at 11332.46,1920.64 h60
  text "MATERIALS AND WORKMANSHIP FOR ALL PCBS" at 12057.46,1920.64 h60
  text "TO MEET OR EXCEED THE REQUIREMENTS OF:" at 12057.46,1822.64 h60
  text "X" at 11683.96,1686.13 h60
  text "ANSI IPC-A-600F CLASS ->" at 11822.96,1686.13 h60
  text "X" at 13462.02,1686.13 h60
  text "2" at 13580.96,1686.14 h60
  text "1" at 13265.96,1684.64 h60
  text "3" at 13934.96,1684.64 h60
  text "X" at 11686.02,1526.64 h60
  text "UL 94V-0" at 11822.96,1526.64 h60
  text "X" at 12498.02,1526.64 h60
  text "RoHS" at 12634.96,1526.64 h60
  text "OTHER" at 13279.36,1526.64 h60
  text "PER ORDER" at 13676.42,1526.64 h60
  text "ADDITIONAL REQUIREMENTS:" at 11332.46,1385.64 h60
  text "MICROSECTION:" at 11407.23,1270.64 h60
  text "YES" at 12312.96,1270.64 h60
  text "REQUIRED" at 13174.46,1114.49 h60
  text "BARE BOARD ELEC. TEST:" at 11407.23,1111.64 h60
  text "NONE" at 12712.96,1111.64 h60
  text "X" at 13047.46,1111.64 h60
  text "PER ORDER" at 13766.46,1111.64 h60
  text "MANUFACTURER'S UL:" at 11407.23,954.64 h60
  text "RAIL" at 12572.96,950.35 h60
  text "METAL" at 13064.77,950.35 h60
  text "X" at 13440,950 h60
  text "SILK" at 13576.46,950.35 h60
M11 Gerber Information:
  lines w10: -292,-930.17 6308,-930.17 ; -292,-726.83 6310,-726.83 ; -292,-523.5 -292,-1133.5 3713,-1133.5 6310,-1133.5 6310,-523.5 -291.5,-523.5 -291.5,-1133.5 1284,-1133.5 ; 2173,-1133.5 2173,-523.5 ; 3440,-726.83 3440,-523.5 ; 4280,-726.83 4280,-523.5 ; 4902,-1140 4902,-937.17
  text "ALL ARTWORK VIEWED FROM TOP SIDE" at -228.5,-655.67 h40
  text "BOARD #:" at 2248,-655.67 h40
  text ".PRJ_Number" at 2793.5,-655.67 h40
  text "REV:" at 3638,-655.67 h40
  text "E3" at 3929.5,-655.67 h40
  text "SVN REV:" at 4476,-655.67 h40
  text ".VersionControl_RevNumber" at 4982,-655.67 h40
  text ".PRJ_Title" at 2244,-854 h40
  text "LAYER NAME =" at -228.5,-858.49 h40
  text "PLOT NAME =" at -228.5,-1064.34 h40
  text ".plot_File_Name" at 577,-1064.34 h40
  text "GENERATED    :" at 2250,-1064.34 h40
  text ".Print_Date" at 3119.5,-1064.34 h40
  text ".Print_Time" at 3848.5,-1064.34 h40
  text "TEXAS INSTRUMENTS" at 5113,-1064.34 h40
M12 Stackup:
  lines w6: 11365,7701.75 14235,7701.75 ; 11365,7818.45 14235,7818.45 ; 11305,6968 ccw(c11343,6968) 11343,6930 14257,6930 ccw(c14257,6968) 14295,6968 14295,7917 ccw(c14257,7917) 14257,7955 11343,7955 ccw(c11343,7917) 11305,7917 11305,6968
  text "Layer Stack Up Detail for: ISE3010-FMB-E3.PcbDoc" at 11365,7848.12 h52
  text "Layer" at 11365,7774.95 h27
  text "Gerber" at 12371.46,7774.95 h27
  text "Copper" at 13011.23,7774.95 h27
  text "Dielectric" at 13695.1,7774.95 h27
  text "Name" at 11365,7720.95 h27
  text "Document" at 12371.46,7720.95 h27
  text "Thickness" at 13011.23,7720.95 h27
  text "Material" at 13695.1,7720.95 h27
  text "Top Solder Mask" at 11365,7645.36 h38
  text "(.GTS)" at 12371.46,7645.36 h38
  text "Solder Resist" at 13695.1,7645.36 h38
  text "Top Layer" at 11365,7538.59 h38
  text "(.GTL)" at 12371.46,7538.59 h38
  text "1.4mil" at 13011.23,7538.59 h38
  text "FR-4" at 13695.1,7485.21 h38
  text "MidLayer1" at 11365,7431.82 h38
  text "(.G1)" at 12371.46,7431.82 h38
  text "1.4mil" at 13011.23,7431.82 h38
  text "FR-4" at 13695.1,7378.44 h38
  text "MidLayer2" at 11365,7325.05 h38
  text "(.G2)" at 12371.46,7325.05 h38
  text "1.4mil" at 13011.23,7325.05 h38
  text "FR-4" at 13695.1,7271.67 h38
  text "Bottom Layer" at 11365,7218.28 h38
  text "(.GBL)" at 12371.46,7218.28 h38
  text "1.4mil" at 13011.23,7218.28 h38
  text "Bottom Solder Mask" at 11365,7111.51 h38
  text "(.GBS)" at 12371.46,7111.51 h38
  text "Solder Resist" at 13695.1,7111.51 h38
M13 Component Bodies Top:
  text ".Layer_Name" at 577,-858.49 h40
M14 Component Bodies Bottom:
  text ".Layer_Name" at 577,-858.49 h40
M15 Courtyards Top:
  text ".Layer_Name" at 577,-858.49 h40
M16 Courtyards Bottom:
  text ".Layer_Name" at 577,-858.49 h40
Drill Drawing:
  text ".legend" at 52.5,3750.5 h40
  text "Drill Table" at 77.5,3565.5 h40
  text "DRILL TOLERANCES:" at 77.73,3406.9 h40
  text "FOR PTH +/-3MILS" at 852,3396 h40
  text "FOR NPTH +/-2MILS" at 849,3287 h40
  text "DRILL TOLERANCES FOR 8 MIL VIA: +0/-8mils" at 78,3169 h40
  text "DRILL TOLERANCES FOR 12 MIL VIA: +0/-12mils" at 75,3062 h40
  text "DRILL TOLERANCES FOR 16 MIL VIA: +0/-16mils" at 72,2958 h40
  text ".Layer_Name" at 577,-858.49 h40

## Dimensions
0,0 to 0,2362.2 on M2 Board Dimensions
0,0 to 7874.02,0 on M2 Board Dimensions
